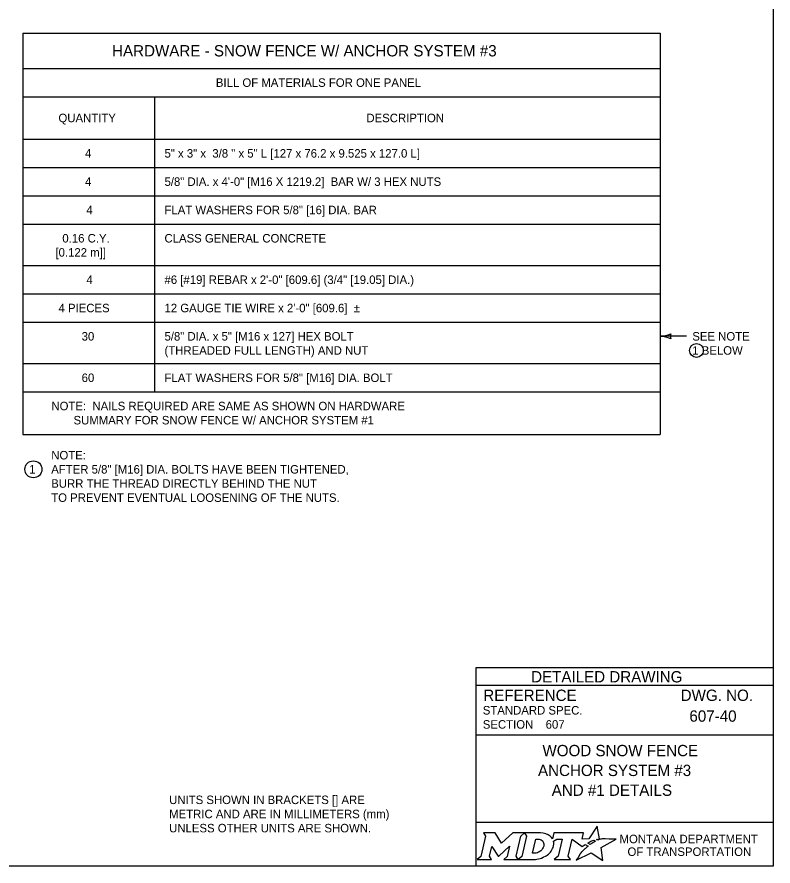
# Model space of a CAD drawing. Extents: x 49991.4 to 50021, y 49987.6 to 50011.4.
# Drawn here: x 50011.41 to 50016.75, y 49987.8 to 49993.8 of the extents above; entities that cross this region are included whole.
import ezdxf

# ---------------------------------------------------------------- set-up
doc = ezdxf.new("R2010")
doc.units = 0
for name, color, linetype in [('Default', 7, 'Continuous'), ('Level 1', 7, 'Continuous'), ('Level 2', 7, 'Continuous'), ('Level 3', 7, 'Continuous'), ('Level 5', 7, 'Continuous')]:
    doc.layers.add(name, color=color, linetype=linetype)

msp = doc.modelspace()

# ---------------------------------------------------------------- linework, layer by layer
at = {"layer": 'Default'}
for points in [[(50015.5126, 49987.9811), (50015.5023, 49987.9867), (50015.5139, 49987.9895), (50015.5255, 49987.9915), (50015.5081, 49988.0816), (50015.4486, 49987.9903), (50015.4013, 49987.9896), (50015.4116, 49988.0337), (50015.2024, 49988.0338), (50015.1923, 49987.9913), (50015.1865, 49987.9996)], [(50014.7056, 49988.0338), (50014.7197, 49988.0104), (50014.6862, 49987.8671), (50014.6605, 49987.8446), (50014.7621, 49987.8446), (50014.7486, 49987.8674), (50014.7648, 49987.9375), (50014.8085, 49987.8685), (50014.8138, 49987.8685), (50014.8889, 49987.938), (50014.8725, 49987.8669), (50014.8478, 49987.8449), (50014.9494, 49987.8449), (50014.9356, 49987.8682), (50014.9688, 49988.0106)], [(50014.9688, 49988.0106), (50014.9941, 49988.0338), (50014.9117, 49988.0338), (50014.8321, 49987.9608), (50014.7876, 49988.0335), (50014.7056, 49988.0338)], [(50015.1077, 49988.0338), (50014.9941, 49988.0338), (50015.0088, 49988.0109), (50014.9749, 49987.8671), (50014.9494, 49987.8449), (50015.06, 49987.8449)], [(50015.1317, 49987.9471), (50015.1305, 49987.939), (50015.1273, 49987.9297), (50015.1231, 49987.9215), (50015.1175, 49987.914), (50015.111, 49987.9071), (50015.1031, 49987.9008), (50015.0948, 49987.8961), (50015.0857, 49987.8922), (50015.0766, 49987.8899), (50015.0674, 49987.889), (50015.0515, 49987.889), (50015.0751, 49987.989), (50015.0911, 49987.989), (50015.0987, 49987.9884), (50015.1063, 49987.9865), (50015.1129, 49987.9835), (50015.119, 49987.9793), (50015.1238, 49987.9743), (50015.1275, 49987.9683), (50015.1302, 49987.9621), (50015.1318, 49987.9547), (50015.1318, 49987.9517), (50015.1317, 49987.9471)], [(50015.1991, 49987.9747), (50015.2237, 49987.9878), (50015.2606, 49987.9878), (50015.232, 49987.8673), (50015.2045, 49987.8446), (50015.3207, 49987.8446), (50015.3037, 49987.8675), (50015.3319, 49987.9877), (50015.4032, 49987.936), (50015.4243, 49987.9511), (50015.444, 49987.9402)], [(50015.3882, 49987.8843), (50015.3729, 49987.8599), (50015.3682, 49987.8524), (50015.3624, 49987.8438), (50015.3601, 49987.8395), (50015.4654, 49987.8926), (50015.5493, 49987.8375), (50015.5362, 49987.9302), (50015.6431, 49987.9886), (50015.5938, 49987.9894), (50015.5637, 49987.9898), (50015.5429, 49987.9901), (50015.5361, 49987.9886), (50015.5312, 49987.9874), (50015.5228, 49987.9851), (50015.5126, 49987.9811)], [(50015.4622, 49987.9535), (50015.4598, 49987.9518), (50015.4415, 49987.9614), (50015.4518, 49987.9671), (50015.4559, 49987.9693), (50015.4645, 49987.9733), (50015.4702, 49987.9759), (50015.4781, 49987.9789), (50015.4854, 49987.9816), (50015.4972, 49987.9742), (50015.4932, 49987.9721), (50015.4886, 49987.9696), (50015.4844, 49987.9674), (50015.4794, 49987.9645), (50015.4775, 49987.9634), (50015.4748, 49987.9618), (50015.4723, 49987.9604), (50015.47, 49987.9588), (50015.4674, 49987.957), (50015.4647, 49987.9552), (50015.4622, 49987.9535)], [(50015.4021, 49987.9004), (50015.4021, 49987.9004)], [(50015.1057, 49987.8522), (50015.1141, 49987.8548), (50015.1271, 49987.8602), (50015.1475, 49987.8712)]]:
    msp.add_lwpolyline(points, dxfattribs=at)
for centre, radius, start, end in [((50015.1308, 49987.9554), 0.0709, 339.53292, 15.85821), ((50015.0868, 49987.9727), 0.1183, 300.91025, 339.13831)]:
    msp.add_arc(centre, radius, start, end, dxfattribs=at)
for centre, major_axis, ratio, start_param, end_param in [((50015.1056, 49987.9864), (0.0834, -0.0037), 0.568097, 0.61298, 1.570796), ((50015.1612, 49987.9937), (0.0361, -0.0295), 0.469099, 1.225588, 1.570796), ((50015.4329, 49987.9305), (-0.0112, -0.0097), 0.021651, 3.157348, 6.283185), ((50015.3952, 49987.8923), (-0.00694, -0.00806), 0.008222, 0, 3.137361), ((50015.4119, 49987.9106), (-0.0098, -0.0102), 0.016458, 3.141593, 6.279097), ((50015.0603, 49987.9932), (0, 0.1484), 0.987302, 3.139398, 3.456847)]:
    msp.add_ellipse(centre, major_axis=major_axis, ratio=ratio, start_param=start_param, end_param=end_param, dxfattribs=at)
at = {"layer": 'Level 1'}
msp.add_lwpolyline([(49999.3835, 49998.9992), (50016.7501, 49998.9992), (50016.7501, 49987.7988), (49999.3835, 49987.7988)], close=True, dxfattribs=at)
at = {"layer": 'Level 2'}
for p, q in [((50011.4523, 49993.6852), (50015.9523, 49993.6852)), ((50011.4523, 49993.6852), (50011.4523, 49990.8492)), ((50015.9523, 49993.6852), (50015.9523, 49990.8492)), ((50011.4523, 49993.4352), (50015.9523, 49993.4352)), ((50011.4523, 49993.2352), (50015.9523, 49993.2352)), ((50012.3822, 49993.2352), (50012.3822, 49991.1492)), ((50011.4523, 49992.9352), (50015.9523, 49992.9352)), ((50011.4523, 49992.7352), (50015.9523, 49992.7352)), ((50011.4523, 49992.5352), (50015.9523, 49992.5352)), ((50011.4523, 49992.3352), (50015.9523, 49992.3352)), ((50011.4523, 49992.0422), (50015.9523, 49992.0422)), ((50011.4523, 49991.8422), (50015.9523, 49991.8422)), ((50011.4523, 49991.6422), (50015.9523, 49991.6422)), ((50011.4523, 49991.3492), (50015.9523, 49991.3492)), ((50011.4523, 49991.1492), (50015.9523, 49991.1492)), ((50011.4523, 49990.8492), (50015.9523, 49990.8492))]:
    msp.add_line(p, q, dxfattribs=at)
for centre, radius in [((50016.2098, 49991.4422), 0.0486), ((50011.526, 49990.6022), 0.06)]:
    msp.add_circle(centre, radius, dxfattribs=at)
at = {"layer": 'Level 3'}
msp.add_line((50016.1399, 49991.5422), (50015.9523, 49991.5422), dxfattribs=at)
for centre, radius, start, end in [((50015.9408, 49991.7749), 0.233, 272.82731, 292.07716), ((50015.9431, 49991.3201), 0.2223, 67.45601, 87.63952), ((50016.0805, 49991.5422), 0.0548, 162.13882, 197.86118)]:
    msp.add_arc(centre, radius, start, end, dxfattribs=at)
at = {"layer": 'Level 5'}
for p, q in [((50016.7501, 49989.1988), (50014.6501, 49989.1988)), ((50014.6501, 49989.1988), (50014.6501, 49987.7988)), ((50016.7501, 49989.0738), (50014.6501, 49989.0738)), ((50016.3862, 49988.8587), (50016.3862, 49988.8587)), ((50015.1444, 49988.7993), (50015.1444, 49988.7993)), ((50016.7501, 49988.7238), (50014.6501, 49988.7238)), ((50015.7001, 49988.4747), (50015.7001, 49988.4747)), ((50016.7501, 49988.1057), (50014.6501, 49988.1057))]:
    msp.add_line(p, q, dxfattribs=at)

# ---------------------------------------------------------------- texts
at = {"layer": 'Default'}
for s, p in [('MONTANA DEPARTMENT', (50015.6663, 49987.96)), ('OF TRANSPORTATION', (50015.7225, 49987.87))]:
    msp.add_text(s, height=0.06, dxfattribs=at).set_placement(p)
at = {"layer": 'Level 2'}
for s, height, p in [('HARDWARE - SNOW FENCE W/ ANCHOR SYSTEM #3', 0.08, (50012.082, 49993.5202)), ('BILL OF MATERIALS FOR ONE PANEL', 0.06, (50012.8151, 49993.3052)), ('QUANTITY', 0.06, (50011.7032, 49993.0552)), ('DESCRIPTION', 0.06, (50013.8783, 49993.0552)), ('4', 0.06, (50011.8907, 49992.8052)), ('5" x 3" x  3/8 " x 5" L [127 x 76.2 x 9.525 x 127.0 L]', 0.06, (50012.4522, 49992.8052)), ('4', 0.06, (50011.8907, 49992.6052)), ('5/8" DIA. x 4\'-0" [M16 X 1219.2]  BAR W/ 3 HEX NUTS', 0.06, (50012.4522, 49992.6052)), ('4', 0.06, (50011.9002, 49992.4052)), ('FLAT WASHERS FOR 5/8" [16] DIA. BAR', 0.06, (50012.4522, 49992.4052)), ('0.16 C.Y.', 0.06, (50011.7307, 49992.2052)), ('CLASS GENERAL CONCRETE', 0.06, (50012.4522, 49992.2052)), ('[0.122 m]]', 0.06, (50011.682, 49992.1052)), ('4', 0.06, (50011.9003, 49991.9122)), ('#6 [#19] REBAR x 2\'-0" [609.6] (3/4" [19.05] DIA.)', 0.06, (50012.4522, 49991.9122)), ('4 PIECES', 0.06, (50011.7037, 49991.7122)), ('12 GAUGE TIE WIRE x 2\'-0" [609.6]  ±', 0.06, (50012.4522, 49991.7122)), ('30', 0.06, (50011.8672, 49991.5122)), ('5/8" DIA. x 5" [M16 x 127] HEX BOLT', 0.06, (50012.4522, 49991.5122)), ('SEE NOTE', 0.06, (50016.1799, 49991.5122)), ('(THREADED FULL LENGTH) AND NUT', 0.06, (50012.4522, 49991.4122)), ('1 BELOW', 0.06, (50016.1799, 49991.4122)), ('60', 0.06, (50011.8672, 49991.2192)), ('FLAT WASHERS FOR 5/8" [M16] DIA. BOLT', 0.06, (50012.4522, 49991.2192)), ('NOTE:  NAILS REQUIRED ARE SAME AS SHOWN ON HARDWARE', 0.06, (50011.6536, 49991.0196)), ('       SUMMARY FOR SNOW FENCE W/ ANCHOR SYSTEM #1', 0.06, (50011.6536, 49990.9196)), ('NOTE:', 0.06, (50011.6523, 49990.6722)), ('1', 0.06, (50011.4959, 49990.5722)), ('AFTER 5/8" [M16] DIA. BOLTS HAVE BEEN TIGHTENED,', 0.06, (50011.6523, 49990.5722)), ('BURR THE THREAD DIRECTLY BEHIND THE NUT', 0.06, (50011.6523, 49990.4722)), ('TO PREVENT EVENTUAL LOOSENING OF THE NUTS.', 0.06, (50011.6523, 49990.3722)), ('607-40', 0.08, (50016.1596, 49988.8187)), ('607', 0.06, (50015.1444, 49988.7693)), ('WOOD SNOW FENCE', 0.08, (50015.1217, 49988.5747)), ('ANCHOR SYSTEM #3', 0.08, (50015.0903, 49988.4347)), ('AND #1 DETAILS', 0.08, (50015.1871, 49988.2947)), ('UNITS SHOWN IN BRACKETS [] ARE ', 0.06, (50012.4851, 49988.2366)), ('METRIC AND ARE IN MILLIMETERS (mm) ', 0.06, (50012.4851, 49988.1366)), ('UNLESS OTHER UNITS ARE SHOWN.', 0.06, (50012.4851, 49988.0366))]:
    msp.add_text(s, height=height, dxfattribs=at).set_placement(p)
at = {"layer": 'Level 5'}
for s, height, p in [('DETAILED DRAWING', 0.0799, (50015.0418, 49989.0963)), ('REFERENCE', 0.08, (50014.7037, 49988.9654)), ('DWG. NO.', 0.08, (50016.0979, 49988.9654)), ('STANDARD SPEC.', 0.06, (50014.7004, 49988.8694)), ('SECTION', 0.06, (50014.7004, 49988.7694))]:
    msp.add_text(s, height=height, dxfattribs=at).set_placement(p)

doc.saveas('drawing.dxf')
